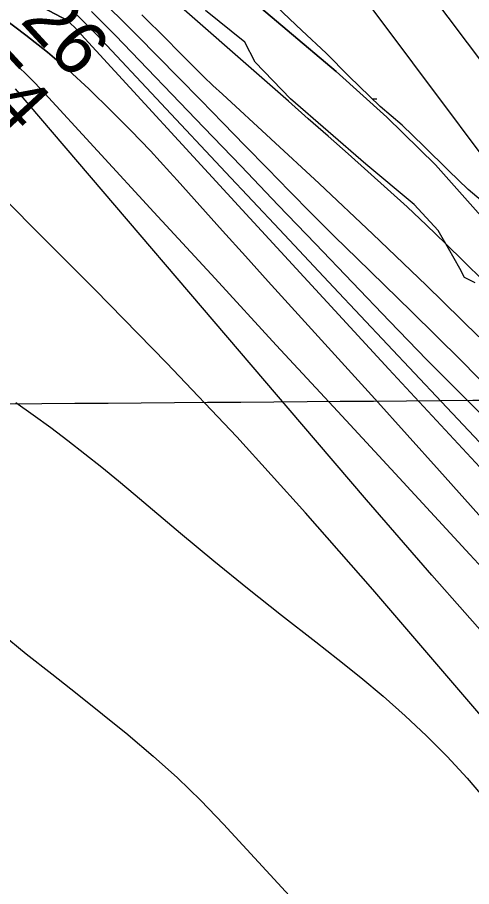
# Model space of a CAD drawing. Extents: x 3540316 to 3578335, y 553172 to 578787.
# Drawn here: x 3551118 to 3551683, y 564084 to 565162 of the extents above; entities that cross this region are included whole.
import ezdxf

# ---------------------------------------------------------------- set-up
doc = ezdxf.new("R2010")
doc.units = 0
for name, color, linetype in [('V-GRID-MAJR', 7, 'Continuous'), ('V-RIVR-EDGE', 7, 'Continuous'), ('V-RIVR-RANG', 7, 'Continuous'), ('V-TOPO-DPTH', 7, 'Continuous'), ('V-TOPO-MAJR', 7, 'Continuous'), ('V-TOPO-MINR', 7, 'Continuous'), ('V-TOPO-WATR', 7, 'Continuous'), ('V-WETL-SWMP', 7, 'Continuous')]:
    doc.layers.add(name, color=color, linetype=linetype)

msp = doc.modelspace()

# ---------------------------------------------------------------- linework, layer by layer
at = {"layer": 'V-GRID-MAJR'}
msp.add_spline([(3544475.4, 564634.2), (3549748.1, 564672.9), (3555020.8, 564712.4), (3560293.6, 564752.7), (3565566.3, 564793.7), (3570839, 564835.5), (3576111.7, 564878.1)], degree=3, dxfattribs=at)
at = {"layer": 'V-RIVR-EDGE'}
msp.add_lwpolyline([(3551686.9, 564833.1), (3551673.5, 564839.9), (3551668, 564851), (3551653.9, 564875.5), (3551641.1, 564898.2), (3551611.2, 564930.1), (3551551.3, 564980.5), (3551457.7, 565061.6), (3551413.7, 565107.1), (3551400.9, 565131.6), (3551352, 565171)], dxfattribs=at)
at = {"layer": 'V-TOPO-DPTH'}
for points in [[(3550497.6, 565518.5), (3551180.6, 565158.7), (3551185, 565154.5), (3551189.4, 565150.2), (3551193.6, 565145.8), (3551197.8, 565141.4), (3551397.8, 564923.6), (3551488.8, 564824.8), (3551579.8, 564726), (3551671.1, 564627.4), (3551762.5, 564528.9)], [(3551762.5, 564528.9), (3551671.1, 564627.4), (3551579.8, 564726), (3551488.8, 564824.8), (3551397.8, 564923.6), (3551197.8, 565141.4), (3551193.6, 565145.8), (3551189.4, 565150.2), (3551185, 565154.5), (3551180.6, 565158.7), (3550497.6, 565518.5)], [(3551392.8, 565198.5), (3551514.2, 565095.5), (3551577.2, 565038.7), (3551637.5, 564979.4), (3551694.1, 564916.4), (3551748.1, 564851), (3552175.2, 564299.5), (3552193.6, 564275.1), (3552211.6, 564250.5), (3552229, 564225.4), (3552246, 564200), (3552294.7, 564125.5), (3552318.6, 564088.6), (3552342.3, 564051.6)], [(3551101.8, 565161.2), (3551129.1, 565140.5), (3551156, 565119.2), (3551181.9, 565096.8), (3551207.2, 565073.7), (3551208.8, 565072.1), (3551234.3, 565047.4), (3551259.3, 565022.3), (3551283.7, 564996.7), (3551307.7, 564970.6), (3551316.8, 564960.4), (3551345.1, 564929), (3551373.4, 564897.6), (3551401.7, 564866.3), (3551430.1, 564834.9), (3551562.2, 564689.3), (3551642.8, 564599.9), (3551723, 564510.2)], [(3551101.8, 565161.2), (3551129.1, 565140.5), (3551156, 565119.2), (3551181.9, 565096.8), (3551207.2, 565073.7), (3551208.8, 565072.1), (3551234.3, 565047.4), (3551259.3, 565022.3), (3551283.7, 564996.7), (3551307.7, 564970.6), (3551316.8, 564960.4), (3551345.1, 564929), (3551373.4, 564897.6), (3551401.7, 564866.3), (3551430.1, 564834.9), (3551562.2, 564689.3), (3551642.8, 564599.9), (3551723, 564510.2)], [(3552220.9, 564070.5), (3552209.1, 564086.2), (3552159, 564152.1), (3552141.3, 564174.9), (3552123.2, 564197.4), (3552104.7, 564219.6), (3552085.9, 564241.5), (3551916, 564435.4), (3551869.5, 564487.3), (3551822.4, 564538.6), (3551774.2, 564589), (3551725.3, 564638.7), (3551720.9, 564643.1), (3551673.9, 564690.2), (3551627.1, 564737.6), (3551580.7, 564785.4), (3551534.5, 564833.4), (3551488.5, 564881.5), (3551442.4, 564929.6), (3551396.3, 564977.7), (3551350.2, 565025.7), (3551240.2, 565140.2), (3551225.6, 565155.1), (3551210.7, 565169.7)], [(3551210.7, 565169.7), (3551225.6, 565155.1), (3551240.2, 565140.2), (3551350.2, 565025.7), (3551396.3, 564977.7), (3551442.4, 564929.6), (3551488.5, 564881.5), (3551534.5, 564833.4), (3551580.7, 564785.4), (3551627.1, 564737.6), (3551673.9, 564690.2), (3551720.9, 564643.1), (3551725.3, 564638.7), (3551774.2, 564589), (3551822.4, 564538.6), (3551869.5, 564487.3), (3551916, 564435.4), (3552085.9, 564241.5), (3552104.7, 564219.6), (3552123.2, 564197.4), (3552141.3, 564174.9), (3552159, 564152.1), (3552209.1, 564086.2), (3552220.9, 564070.5)], [(3551691.5, 564766), (3551626.2, 564830.2), (3551560, 564893.5), (3551493.1, 564956.2), (3551373, 565067), (3551361.4, 565077.9), (3551350, 565088.8), (3551338.7, 565099.9), (3551327.6, 565111.1), (3551316.4, 565122.3), (3551305.3, 565133.6), (3551294.1, 565144.8), (3551282.9, 565155.9), (3551273.2, 565165.6)], [(3551691.5, 564766), (3551626.2, 564830.2), (3551560, 564893.5), (3551493.1, 564956.2), (3551373, 565067), (3551361.4, 565077.9), (3551350, 565088.8), (3551338.7, 565099.9), (3551327.6, 565111.1), (3551316.4, 565122.3), (3551305.3, 565133.6), (3551294.1, 565144.8), (3551282.9, 565155.9), (3551273.2, 565165.6)], [(3552185, 563857.7), (3552014.2, 564111.3), (3552009, 564118.7), (3552003.8, 564126), (3551998.4, 564133.2), (3551992.8, 564140.3), (3551934.1, 564213), (3551903.9, 564249.6), (3551873.2, 564285.9), (3551841.7, 564321.5), (3551809.7, 564356.6), (3551777.3, 564391.4), (3551744.9, 564426.3), (3551712.6, 564461.1), (3551680.3, 564496), (3551592.4, 564590.9), (3551516.2, 564673.3), (3551440, 564755.8), (3551364, 564838.3), (3551287.9, 564920.9), (3551148.2, 565072.8), (3551138.1, 565083.4), (3551127.7, 565093.6), (3551116.9, 565103.5)], [(3551116.9, 565103.5), (3551127.7, 565093.6), (3551138.1, 565083.4), (3551148.2, 565072.8), (3551287.9, 564920.9), (3551364, 564838.3), (3551440, 564755.8), (3551516.2, 564673.3), (3551592.4, 564590.9), (3551680.3, 564496), (3551712.6, 564461.1), (3551744.9, 564426.3), (3551777.3, 564391.4), (3551809.7, 564356.6), (3551841.7, 564321.5), (3551873.2, 564285.9), (3551903.9, 564249.6), (3551934.1, 564213), (3551992.8, 564140.3), (3551998.4, 564133.2), (3552003.8, 564126), (3552009, 564118.7), (3552014.2, 564111.3), (3552185, 563857.7)]]:
    msp.add_lwpolyline(points, dxfattribs=at)
at = {"layer": 'V-TOPO-MAJR'}
msp.add_lwpolyline([(3551979.5, 564081.5), (3551962.4, 564101.2), (3551945.2, 564120.7), (3551927.8, 564140.2), (3551797.3, 564285.4), (3551715, 564377.7), (3551633.2, 564470.4), (3551552.1, 564563.7), (3551471.5, 564657.5), (3551116.3, 565074)], dxfattribs=at)
at = {"layer": 'V-TOPO-MINR'}
for points in [[(3552450.7, 564051), (3552413.6, 564114.4), (3552376.1, 564177.7), (3552333.3, 564249.2), (3552316.6, 564276.3), (3552299.3, 564303), (3552281.1, 564329.1), (3552262.3, 564354.8), (3551604.2, 565228.5), (3551581.5, 565257.9), (3551558.3, 565286.8), (3551534.2, 565315.1), (3551509.7, 565343), (3551484.6, 565370.4), (3551459, 565397.3), (3551433, 565423.8), (3551406.5, 565449.9), (3550894.9, 565944.3)], [(3551883.3, 564075.7), (3551559.8, 564452.5), (3551476.1, 564547.8), (3551390.9, 564641.9), (3551303.6, 564733.9), (3551214.9, 564824.6), (3551035.7, 565003.7), (3551035.5, 565003.9), (3551035.1, 565004.3), (3551032.5, 565005.6), (3551030.4, 565006.4), (3550284.8, 565467), (3550274.7, 565472.7), (3550264.3, 565478.1), (3550191.2, 565514.4), (3550184.7, 565517.3), (3550178.1, 565519.9), (3550171.3, 565522.1), (3550164.4, 565523.9), (3549630.9, 565679)], [(3551762.5, 564528.9), (3551671.1, 564627.4), (3551579.8, 564726), (3551488.8, 564824.8), (3551397.8, 564923.6), (3551197.8, 565141.4), (3551193.6, 565145.8), (3551189.4, 565150.2), (3551185, 565154.5), (3551180.6, 565158.7), (3550497.6, 565518.5)], [(3552460.9, 563917), (3552321.3, 564130.6), (3552314.1, 564141.7), (3552307, 564152.8), (3552299.8, 564163.9), (3552292.7, 564175), (3552285.6, 564186.2), (3552278.5, 564197.3), (3552271.4, 564208.4), (3552264.2, 564219.4), (3552256.7, 564230.9), (3552245.6, 564247.6), (3552234.3, 564264.1), (3552222.8, 564280.5), (3552211.1, 564296.8), (3552124.8, 564414.9), (3552069.6, 564490), (3552014.3, 564565), (3551958.8, 564639.8), (3551903.1, 564714.4), (3551433.3, 565341.9)], [(3552315.3, 564047.4), (3552210.8, 564208.1), (3552200.8, 564223.1), (3552190.6, 564237.9), (3552180, 564252.5), (3552169.2, 564266.9), (3551936.9, 564569.1), (3551885.8, 564632.9), (3551832.8, 564695.1), (3551777.3, 564755), (3551720.1, 564813.3), (3551650.1, 564881.7), (3551626.4, 564904.6), (3551602.5, 564927.2), (3551578.2, 564949.4), (3551553.8, 564971.4), (3551529.1, 564993.2), (3551504.4, 565015), (3551479.7, 565036.8), (3551455, 565058.5), (3551282.6, 565210)], [(3552342.3, 564051.6), (3552318.6, 564088.6), (3552294.7, 564125.5), (3552246, 564200), (3552229, 564225.4), (3552211.6, 564250.5), (3552193.6, 564275.1), (3552175.2, 564299.5), (3551748.1, 564851), (3551694.1, 564916.4), (3551637.5, 564979.4), (3551577.2, 565038.7), (3551514.2, 565095.5), (3551392.8, 565198.5)], [(3551730, 564675.2), (3551669.4, 564736.8), (3551608, 564797.6), (3551540.6, 564863.1), (3551512.4, 564890.7), (3551484.3, 564918.6), (3551456.5, 564946.7), (3551428.9, 564974.9), (3551401.4, 565003.2), (3551373.8, 565031.6), (3551346.2, 565059.8), (3551318.5, 565088), (3551267.4, 565139.9), (3551246, 565161.1), (3551224.1, 565182)], [(3551723, 564510.2), (3551642.8, 564599.9), (3551562.2, 564689.3), (3551430.1, 564834.9), (3551401.7, 564866.3), (3551373.4, 564897.6), (3551345.1, 564929), (3551316.8, 564960.4), (3551307.7, 564970.6), (3551283.7, 564996.7), (3551259.3, 565022.3), (3551234.3, 565047.4), (3551208.8, 565072.1), (3551207.2, 565073.7), (3551181.9, 565096.8), (3551156, 565119.2), (3551129.1, 565140.5), (3551101.8, 565161.2)], [(3552248, 563984.7), (3552119.8, 564159.2), (3552110.4, 564171.8), (3552100.9, 564184.1), (3552091.1, 564196.3), (3552081.1, 564208.4), (3551979.2, 564328.9), (3551947.3, 564365.8), (3551914.9, 564402.2), (3551881.6, 564437.9), (3551847.9, 564473.1), (3551813.8, 564508.1), (3551779.9, 564543.1), (3551746.2, 564578.4), (3551712.6, 564613.8), (3551645.3, 564685.3), (3551578.2, 564756.5), (3551511.1, 564827.8), (3551444, 564899.1), (3551377, 564970.4), (3551217.1, 565140.8), (3551208.2, 565150), (3551199.1, 565159.1), (3551189.8, 565168)], [(3552220.9, 564070.5), (3552209.1, 564086.2), (3552159, 564152.1), (3552141.3, 564174.9), (3552123.2, 564197.4), (3552104.7, 564219.6), (3552085.9, 564241.5), (3551916, 564435.4), (3551869.5, 564487.3), (3551822.4, 564538.6), (3551774.2, 564589), (3551725.3, 564638.7), (3551720.9, 564643.1), (3551673.9, 564690.2), (3551627.1, 564737.6), (3551580.7, 564785.4), (3551534.5, 564833.4), (3551488.5, 564881.5), (3551442.4, 564929.6), (3551396.3, 564977.7), (3551350.2, 565025.7), (3551240.2, 565140.2), (3551225.6, 565155.1), (3551210.7, 565169.7)], [(3552185, 563857.7), (3552014.2, 564111.3), (3552009, 564118.7), (3552003.8, 564126), (3551998.4, 564133.2), (3551992.8, 564140.3), (3551934.1, 564213), (3551903.9, 564249.6), (3551873.2, 564285.9), (3551841.7, 564321.5), (3551809.7, 564356.6), (3551777.3, 564391.4), (3551744.9, 564426.3), (3551712.6, 564461.1), (3551680.3, 564496), (3551592.4, 564590.9), (3551516.2, 564673.3), (3551440, 564755.8), (3551364, 564838.3), (3551287.9, 564920.9), (3551148.2, 565072.8), (3551138.1, 565083.4), (3551127.7, 565093.6), (3551116.9, 565103.5)], [(3551116.4, 564684.6), (3551138.3, 564669.2), (3551159.9, 564653.4), (3551181.3, 564637.3), (3551202.4, 564620.9), (3551223.4, 564604.2), (3551244.1, 564587.3), (3551264.7, 564570.2), (3551321.2, 564522.5), (3551362.6, 564488.1), (3551404.3, 564454), (3551446.4, 564420.5), (3551488.9, 564387.4), (3551516.5, 564366.1), (3551545, 564343.4), (3551572.9, 564320.1), (3551600.1, 564295.9), (3551626.7, 564271), (3551652.3, 564245.1), (3551677, 564218.4), (3551700.6, 564190.7), (3551723.4, 564162.3), (3551821, 564034.6)], [(3551098.4, 564398.3), (3551129.5, 564372.8), (3551161.2, 564348), (3551192.8, 564323), (3551224.3, 564297.9), (3551255.6, 564272.6), (3551256.2, 564272.2), (3551287.2, 564245.9), (3551317.3, 564218.9), (3551346.3, 564190.5), (3551374.4, 564161.3), (3551577, 563941.6)]]:
    msp.add_lwpolyline(points, dxfattribs=at)
at = {"layer": 'V-TOPO-WATR'}
msp.add_lwpolyline([(3551691.5, 564766), (3551626.2, 564830.2), (3551560, 564893.5), (3551493.1, 564956.2), (3551373, 565067), (3551361.4, 565077.9), (3551350, 565088.8), (3551338.7, 565099.9), (3551327.6, 565111.1), (3551316.4, 565122.3), (3551305.3, 565133.6), (3551294.1, 565144.8), (3551282.9, 565155.9), (3551273.2, 565165.6)], dxfattribs=at)
at = {"layer": 'V-WETL-SWMP'}
for p, q in [((3551471.8, 565146.1), (3551432.9, 565183)), ((3551501.9, 565118), (3551471.8, 565146.1)), ((3551530, 565089.4), (3551501.9, 565118)), ((3551569, 565052), (3551530, 565089.4)), ((3551559.3, 565061.3), (3551564.9, 565061.4)), ((3551596.1, 565028.8), (3551569, 565052)), ((3551623.2, 565002.6), (3551596.1, 565028.8)), ((3551653.8, 564972.5), (3551623.2, 565002.6)), ((3551678.4, 564948.8), (3551653.8, 564972.5)), ((3551738.5, 564897.4), (3551678.4, 564948.8))]:
    msp.add_line(p, q, dxfattribs=at)

# ---------------------------------------------------------------- texts
at = {"layer": 'V-RIVR-RANG'}
for s, p in [('-26', (3551100.7, 565179.4)), ('-54', (3551027.8, 565110.9))]:
    msp.add_text(s, height=67, rotation=312.6426, dxfattribs=at).set_placement(p)

doc.saveas('drawing.dxf')
